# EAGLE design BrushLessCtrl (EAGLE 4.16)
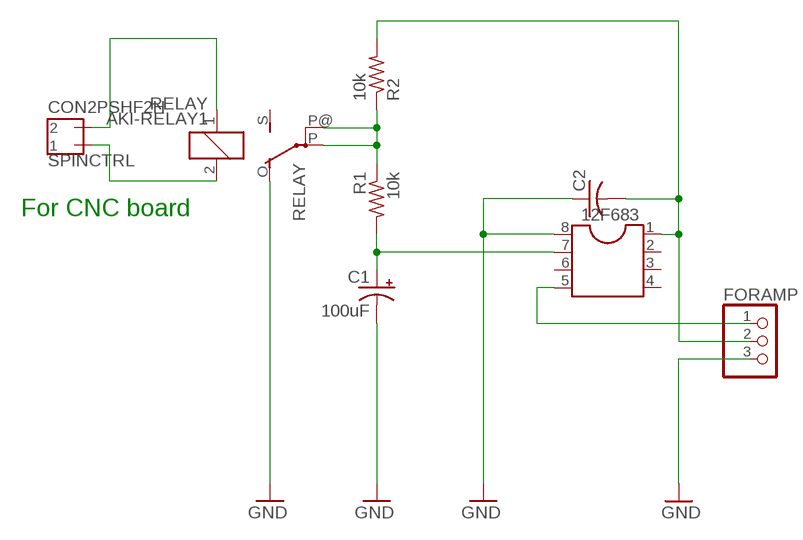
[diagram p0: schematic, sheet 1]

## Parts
12F683  DIL8  [DIL08]
C1  100uF  CPOL-USE5-8.5  [E5-8,5]
C2  C-US025-024X044  [C025-024X044]
FORAMP  PINHD-1X3  [1X03]
R1  10k  R-US_0204/5  [0204/5]
R2  10k  R-US_0204/5  [0204/5]
RELAY  AKI-RELAY1  [FSMR]
SPINCTRL  CON2PSHF2H  [HJST_SHF_2]

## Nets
GND: 12F683.8 C1.- C2.1 FORAMP.3 RELAY.O(O1)
N$1: 12F683.1 C2.2 FORAMP.2 R2.2
N$2: 12F683.5 FORAMP.1
N$3: 12F683.7 C1.+ R1.2
N$5: RELAY.1 SPINCTRL.P$2
N$6: RELAY.2 SPINCTRL.P$1
N$7: R1.1 R2.1 RELAY.P(P1) RELAY.P@(P)
Unconnected: 12F683.2 12F683.3 12F683.4 12F683.6 RELAY.S

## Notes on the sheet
- For CNC board

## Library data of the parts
12F683 = 89 dil:DIL8: SOCKET Dual In Line
C1 = 05 myrcl:CPOL-US: POLARIZED CAPACITOR, American symbol
C2 = 05 myrcl:C-US: CAPACITOR, American symbol
FORAMP = 82 pinhead:PINHD-1X3: PIN HEADER
R1 R2 = 05 myrcl:R-US_: RESISTOR, American symbol
RELAY = 01 MyLibs:AKI-RELAY1: Akizuki Small Relay 4VDC 1A 1circuit
SPINCTRL = 01 MyLibs:CON2P: AKIZUKI DC Connector 2.1mm

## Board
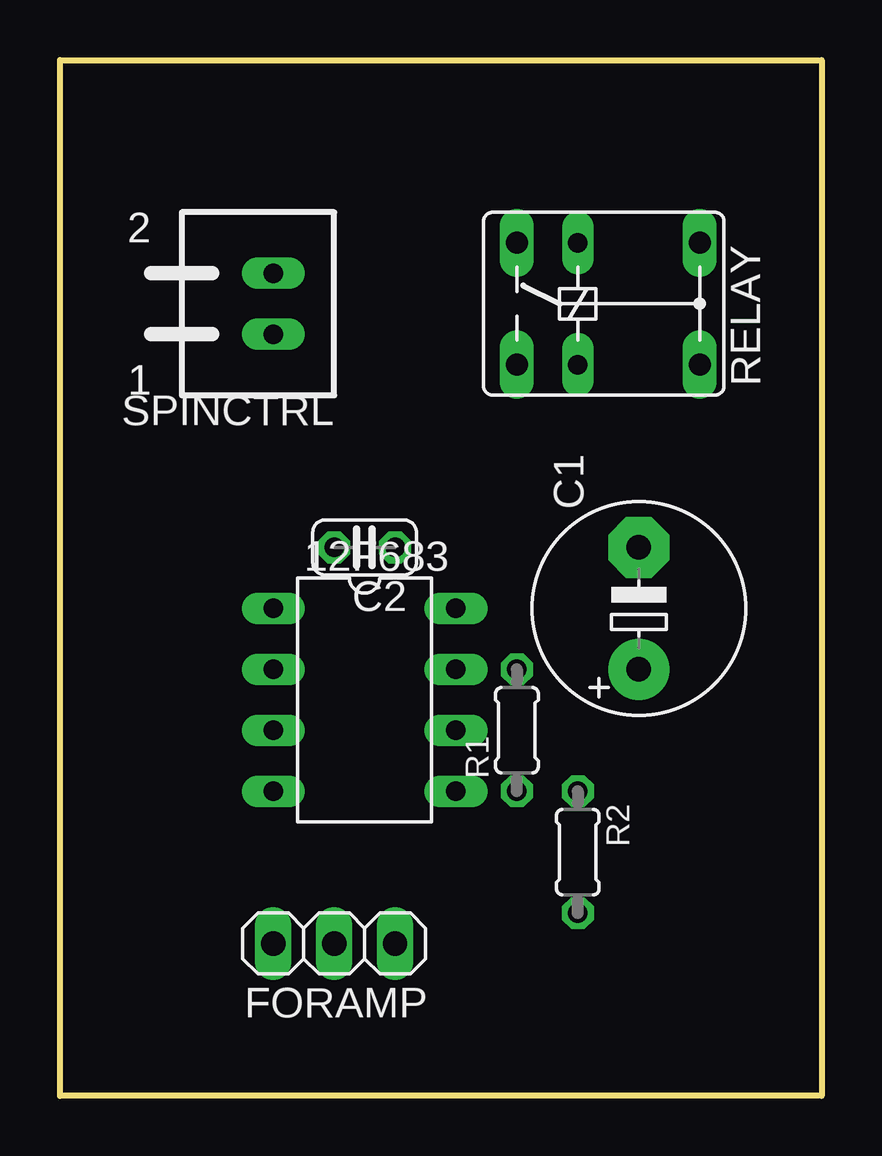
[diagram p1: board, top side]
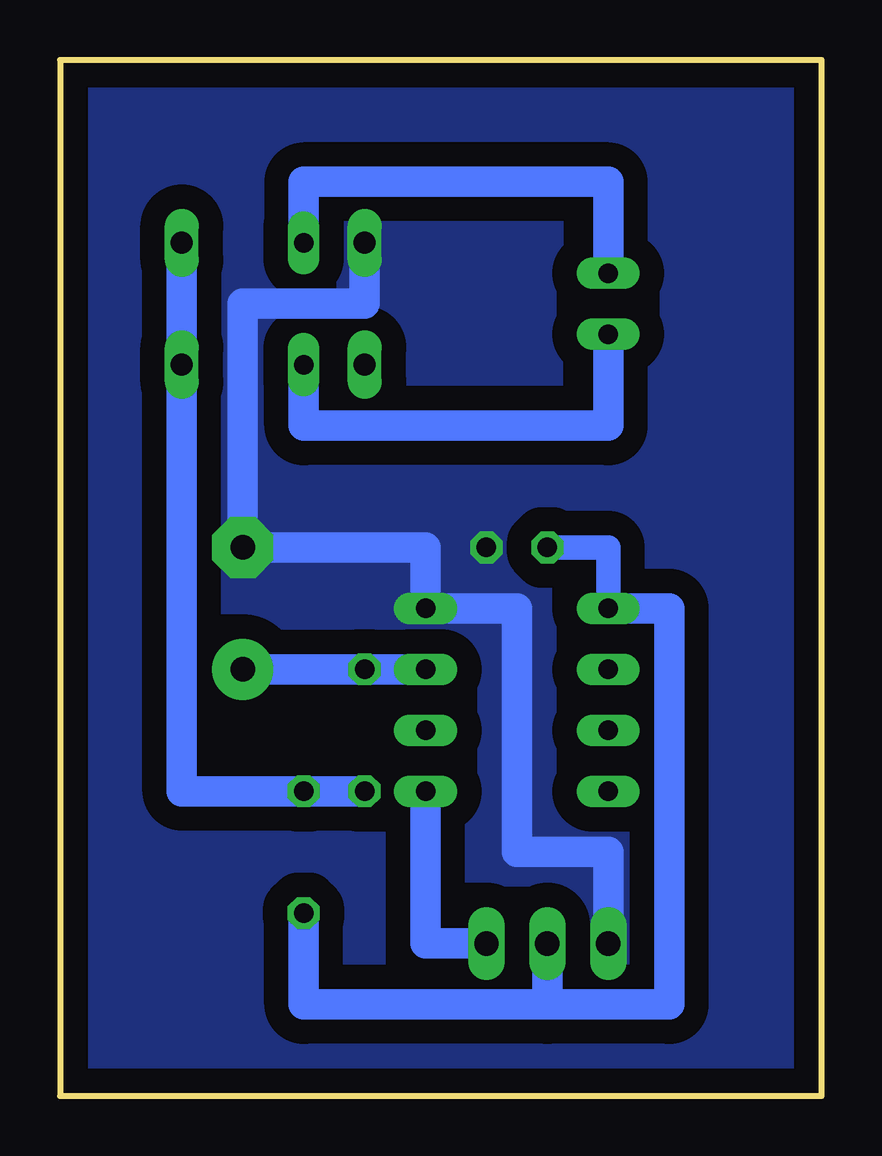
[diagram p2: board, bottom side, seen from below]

Size 31.75 x 43.18 mm. Coordinates in mm from the lower left corner, seen from the top.
Outline: 0,0 0,43.18 31.75,43.18 31.75,0 0,0
Copper layers (1*16): Top 0.035mm / dielectric 1.5mm / Bottom 0.035mm
Design rules "default": minimum track width 10mil, minimum drill 24mil, track to track 8mil, track to pad 8mil, pad to pad 8mil, via to via 8mil, smd to smd 8mil, copper to edge 40mil, drill to drill 8mil, minimum pad ring 10mil, minimum via ring 8mil, stop-mask expansion 4mil, vias tented up to drill 0mil, thermal gap 10mil

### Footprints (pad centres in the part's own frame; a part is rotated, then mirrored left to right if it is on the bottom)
DIL08 = drill 0.813 long: 1 -3.81,-3.81; 2 -1.27,-3.81; 3 1.27,-3.81; 4 3.81,-3.81; 5 3.81,3.81; 6 1.27,3.81; 7 -1.27,3.81; 8 -3.81,3.81
E5-8,5 = drill 1.016 pad 2.54 round: + -2.54,0 | drill 1.016 pad 2.54 octagon: - 2.54,0
C025-024X044 = drill 0.813 octagon: 1 -1.27,0; 2 1.27,0
1X03 = drill 1.016 long: 1 -2.54,0; 2 0,0; 3 2.54,0
0204/5 = drill 0.813 octagon: 1 -2.54,0; 2 2.54,0
FSMR = drill 0.813 long: 1 0,2.54; 2 0,-2.54 | drill 0.914 long: O -2.54,2.54; P 5.08,2.54; P@ 5.08,-2.54; S -2.54,-2.54
HJST_SHF_2 = drill 0.813 long: P$1 2.54,2.54; P$2 2.54,0

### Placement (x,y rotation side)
12F683  12.7,16.51 270 top
C1  24.13,20.32 90 top
C2  12.7,22.86 180 top
FORAMP  11.43,6.35 180 top
R1  19.05,15.24 90 top
R2  21.59,10.16 270 top
RELAY  21.59,33.02 0 top
SPINCTRL  11.43,34.29 180 top

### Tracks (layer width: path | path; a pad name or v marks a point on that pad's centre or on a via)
GND
  Bottom 1.27: FORAMP.3 8.89,10.16 12.7,10.16 12.7,20.32 12F683.8 16.51,22.86 C1.- 24.13,33.02 19.05,33.02 RELAY.O
  pour Bottom (isolate 1.016, no thermals): -1.27,44.45 33.02,44.45 33.02,-1.27 -1.27,-1.27
N$1
  Bottom 1.016: C2.2 8.89,22.86 12F683.1
  Bottom 1.27: 12F683.1 6.35,20.32 6.35,3.81 11.43,3.81 | 11.43,3.81 FORAMP.2 | R2.2 21.59,3.81 11.43,3.81
N$2
  Bottom 1.27: FORAMP.1 16.51,6.35 12F683.5
N$3
  Bottom 1.27: 12F683.7 R1.2 C1.+
N$5
  Bottom 1.27: SPINCTRL.P$2 8.89,38.1 21.59,38.1 RELAY.1
N$6
  Bottom 1.27: RELAY.2 21.59,27.94 8.89,27.94 SPINCTRL.P$1
N$7
  Bottom 1.27: R1.1 R2.1 26.67,12.7 RELAY.P RELAY.P@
